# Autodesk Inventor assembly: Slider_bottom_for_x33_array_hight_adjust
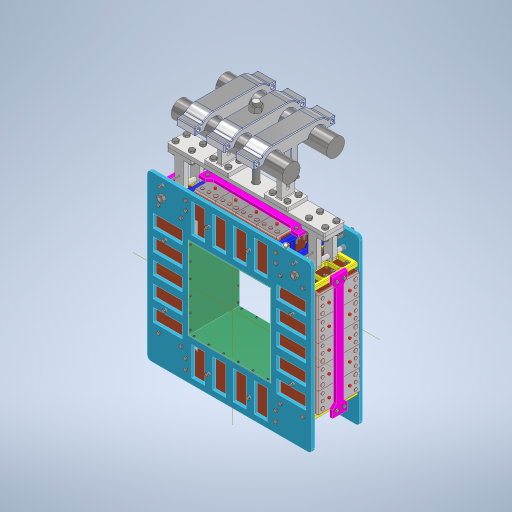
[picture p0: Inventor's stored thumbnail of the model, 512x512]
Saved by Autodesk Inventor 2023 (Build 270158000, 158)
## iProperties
Created: 2022-09
Part Number: Slider_bottom_for_x33_array_hight_adjust
Material: Aluminum 6061
Document SubType Name: Modeling
Designer: tornqvih
Mass: 680.873 g
Surface Area: 393.631 cm^2
Volume: 252.175 cm^3
Density: 2.7 g/cm^3
Appearance: Default
Sending System: Autodesk Inventor 2021
Preprocessor: ST-DEVELOPER v18.1
Title: C:\Users\Oleksii\Documents\Inventor\Scintillators_for_ISS\Part\ISSKUL9_v2.stp
Author: Oleksii
Part Number: Slider_bottom_for_x33_array
Mass: 854.06 g
Surface Area: 503.636 cm^2
Volume: 316.319 cm^3
Title: C:\Users\Oleksii\Documents\Inventor\Scintillators_for_ISS\Part\ISSKUL8_v2.stp
Created: 2023-10
Part Number: CeBr3Holder4x5
Document SubType Name: Assembly
Mass: 47327.2 g
Surface Area: 29304.1 cm^2
Volume: 17682.9 cm^3
Density: 2.67644 g/cm^3
Author: tornqvih
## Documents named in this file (37)
- \\Mac\Home\Documents\chalmers\Inventor2023\CeBr3Holder4x5\CeBr3Holder4x5.iam
- \\Mac\Home\Documents\chalmers\Inventor2023\CeBr3Holder4x5\FrontPlate.ipt
- \\Mac\Home\Documents\chalmers\Inventor2023\CeBr3Holder4x5\ShieldTop.ipt
- \\Mac\Home\Documents\chalmers\Inventor2023\CeBr3Holder4x5\ShieldLeft.ipt
- \\Mac\Home\Documents\chalmers\Inventor2023\CeBr3Holder4x5\SupportHorizontal.ipt
- \\Mac\Home\Documents\chalmers\Inventor2023\CeBr3Holder4x5\SupportVertical.ipt
- \\Mac\Home\Documents\chalmers\Inventor2023\CeBr3Holder4x5\BarHorizontal.ipt
- \\Mac\Home\Documents\chalmers\Inventor2023\CeBr3Holder4x5\BarVertical.ipt
- \\Mac\Home\Documents\chalmers\Inventor2023\CeBr3Holder4x5\CeBr3.ipt
- \\Mac\Home\Documents\Inventor\Content Center Files\R2023\en-US\AS 1110\AS 1110 - M5 x 25.ipt
- \\Mac\Home\Documents\Inventor\Content Center Files\R2023\en-US\AS 1112 (2)\AS 1112 - M5  Type 5.ipt
- \\Mac\Home\Documents\Inventor\Content Center Files\R2023\en-US\AS 1427(05)\AS 1427 - M2.5 x 8(5) II.ipt
- \\Mac\Home\Documents\Inventor\Content Center Files\R2023\en-US\AS 1110\AS 1110 - M5 x 35.ipt
- \\Mac\Home\Documents\Inventor\Content Center Files\R2023\en-US\AS 1110\AS 1110 - M5 x 40.ipt
- \\Mac\Home\Documents\Inventor\Content Center Files\R2023\en-US\ANSI B18.2.4.2M\ANSI B18.2.4.2M - M5x0.8 - 8.ipt
- \\Mac\Home\Documents\chalmers\Inventor2023\CeBr3Holder4x5\PressTopBottom.ipt
- \\Mac\Home\Documents\chalmers\Inventor2023\CeBr3Holder4x5\PressRightLeft.ipt
- \\Mac\Home\Documents\chalmers\Inventor2023\CeBr3Holder4x5\PressSide.ipt
- \\Mac\Home\Documents\Inventor\Content Center Files\R2023\en-US\AS 1474(1)\AS 1474 - M5(1).ipt
- \\Mac\Home\Documents\Inventor\Content Center Files\R2023\en-US\AS 1110\AS 1110 - M5 x 20.ipt
- **\\Mac\Home\Documents\chalmers\Inventor2023\CeBr3Holder4x5\CeBr3Holder4x5.iam*LocalDocs*xAaaaqoaaAaaaaaaaAaaaqnqtPb*ISSKUL8_v2.ipt
- **\\Mac\Home\Documents\chalmers\Inventor2023\CeBr3Holder4x5\CeBr3Holder4x5.iam*LocalDocs*xAaaaarbaAaaaaaaaAaaaqtyoWc*ISSKUL9_v2.ipt
- \\Mac\Home\Documents\chalmers\Inventor2023\CeBr3Holder4x5\HangerSlide.ipt
- \\Mac\Home\Documents\chalmers\Inventor2023\CeBr3Holder4x5\ThreadedRod.ipt
- \\Mac\Home\Documents\Inventor\Content Center Files\R2023\en-US\AS 1112 (2)\AS 1112 - M10  Type 5.ipt
- \\Mac\Home\Documents\chalmers\Inventor2023\CeBr3Holder4x5\HangerSlideHorizontal.ipt
- \\Mac\Home\Documents\chalmers\Inventor2023\CeBr3Holder4x5\HangerHorizontal.ipt
- \\Mac\Home\Documents\chalmers\Inventor2023\CeBr3Holder4x5\Roller.ipt
- \\Mac\Home\Documents\Inventor\Content Center Files\R2023\en-US\AS 1110\AS 1110 - M6 x 60.ipt
- \\Mac\Home\Documents\Inventor\Content Center Files\R2023\en-US\AS 1112 (2)\AS 1112 - M6  Type 5.ipt
- \\Mac\Home\Documents\Inventor\Content Center Files\R2023\en-US\AS 1110\AS 1110 - M8 x 30.ipt
- \\Mac\Home\Documents\Inventor\Content Center Files\R2023\en-US\AS 1112 (2)\AS 1112 - M8  Type 5.ipt
- \\Mac\Home\Documents\Inventor\Content Center Files\R2023\en-US\AS 1110\AS 1110 - M5 x 50.ipt
- \\Mac\Home\Documents\chalmers\Inventor2023\CeBr3Holder4x5\ThreadedHeight.ipt
- \\Mac\Home\Documents\Inventor\Content Center Files\R2023\en-US\AS 1112 (2)\AS 1112 - M16  Type 5.ipt
- \\Mac\Home\Documents\chalmers\Inventor2023\ISSKUL_v2\ISSKUL8_v2.stp
- \\Mac\Home\Documents\chalmers\Inventor2023\ISSKUL_v2\ISSKUL9_v2.stp
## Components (301 placed, 54 different names)
1. FrontPlate
2. BackPlate
3. ShieldTop
4. ShieldBottom
5. ShieldLeft
6. ShieldRight
7. SupportHorizontalTR
8. SupportHorizontalTL
9. SupportHorizontalBL
10. SupportHorizontalBR
11. SupportVerticalTR
12. SupportVerticalTL
13. SupportVerticalBL
14. SupportVerticalBR
15. BarHorizontalTop — Mate:351, Mate:372
16. BarHorizontalBottom — Mate:350
17. BarVerticalRight — Mate:356
18. BarVerticalLeft — Mate:359
19. CeBr3:1 — Mate:138, Mate:139, Mate:140, Mate:143, Mate:151, Mate:351
20. CeBr3:2 — Mate:141, Mate:142, Mate:143, Mate:146, Mate:154
21. CeBr3:3 — Mate:144, Mate:145, Mate:146, Mate:149, Mate:157
22. CeBr3:4 — Mate:147, Mate:148, Mate:149, Mate:160, Mate:269
23. CeBr3:5 — Mate:150, Mate:151, Mate:152, Mate:155, Mate:257, Mate:277
24. CeBr3:6 — Mate:153, Mate:154, Mate:155, Mate:158
25. CeBr3:7 — Mate:156, Mate:157, Mate:158, Mate:161
26. CeBr3:8 — Mate:159, Mate:160, Mate:161
27. CeBr3:9 — Mate:162, Mate:163, Mate:164, Mate:167, Mate:175
28. CeBr3:10 — Mate:165, Mate:166, Mate:167, Mate:170, Mate:178
29. CeBr3:11 — Mate:168, Mate:169, Mate:170, Mate:173, Mate:181
30. CeBr3:12 — Mate:171, Mate:172, Mate:173, Mate:184, Mate:272
31. CeBr3:13 — Mate:174, Mate:175, Mate:176, Mate:179, Mate:260
32. CeBr3:14 — Mate:177, Mate:178, Mate:179, Mate:182
33. CeBr3:15 — Mate:180, Mate:181, Mate:182, Mate:185
34. CeBr3:16 — Mate:183, Mate:184, Mate:185, Mate:350
35. CeBr3:17 — Mate:186, Mate:187, Mate:188, Mate:191, Mate:202, Mate:359
36. CeBr3:18 — Mate:189, Mate:190, Mate:191, Mate:194, Mate:205
37. CeBr3:19 — Mate:192, Mate:193, Mate:194, Mate:197, Mate:208
38. CeBr3:20 — Mate:195, Mate:196, Mate:197, Mate:200, Mate:211
39. CeBr3:21 — Mate:198, Mate:199, Mate:200, Mate:214, Mate:278
40. CeBr3:22 — Mate:201, Mate:202, Mate:203, Mate:206, Mate:266
41. CeBr3:23 — Mate:204, Mate:205, Mate:206, Mate:209
42. CeBr3:24 — Mate:207, Mate:208, Mate:209, Mate:212
43. CeBr3:25 — Mate:210, Mate:211, Mate:212, Mate:215
44. CeBr3:26 — Mate:213, Mate:214, Mate:215
45. CeBr3:27 — Mate:216, Mate:217, Mate:218, Mate:221, Mate:232, Mate:356
46. CeBr3:28 — Mate:219, Mate:220, Mate:221, Mate:224, Mate:235
47. CeBr3:29 — Mate:222, Mate:223, Mate:224, Mate:227, Mate:238
48. CeBr3:30 — Mate:225, Mate:226, Mate:227, Mate:230, Mate:241
49. CeBr3:31 — Mate:228, Mate:229, Mate:230, Mate:244, Mate:275
50. CeBr3:32 — Mate:231, Mate:232, Mate:233, Mate:236, Mate:263
51. CeBr3:33 — Mate:234, Mate:235, Mate:236, Mate:239
52. CeBr3:34 — Mate:237, Mate:238, Mate:239, Mate:242
53. CeBr3:35 — Mate:240, Mate:241, Mate:242, Mate:245
54. CeBr3:36 — Mate:243, Mate:244, Mate:245
55. AS 1110 - Metric M5 x 25:1
56. AS 1110 - Metric M5 x 25:2
57. AS 1110 - Metric M5 x 25:3
58. AS 1110 - Metric M5 x 25:4
59. AS 1110 - Metric M5 x 25:5
60. AS 1110 - Metric M5 x 25:6
61. AS 1110 - Metric M5 x 25:7
62. AS 1110 - Metric M5 x 25:8
63. AS 1110 - Metric M5 x 25:9
64. AS 1110 - Metric M5 x 25:10
65. AS 1110 - Metric M5 x 25:11
66. AS 1110 - Metric M5 x 25:12
67. AS 1110 - Metric M5 x 25:13
68. AS 1110 - Metric M5 x 25:14
69. AS 1110 - Metric M5 x 25:15
70. AS 1110 - Metric M5 x 25:16
71. AS 1110 - Metric M5 x 25:17
72. AS 1110 - Metric M5 x 25:18
73. AS 1110 - Metric M5 x 25:19
74. AS 1110 - Metric M5 x 25:20
75. AS 1110 - Metric M5 x 25:21
76. AS 1110 - Metric M5 x 25:22
77. AS 1110 - Metric M5 x 25:23
78. AS 1110 - Metric M5 x 25:24
79. AS 1110 - Metric M5 x 25:25
80. AS 1110 - Metric M5 x 25:26
81. AS 1110 - Metric M5 x 25:27
82. AS 1110 - Metric M5 x 25:28
83. AS 1110 - Metric M5 x 25:29
84. AS 1110 - Metric M5 x 25:30
85. AS 1110 - Metric M5 x 25:31
86. AS 1110 - Metric M5 x 25:32
87. AS 1112 (2) - Metric M5  Type 5:1
88. AS 1112 (2) - Metric M5  Type 5:2
89. AS 1112 (2) - Metric M5  Type 5:3
90. AS 1112 (2) - Metric M5  Type 5:4
91. AS 1112 (2) - Metric M5  Type 5:5
92. AS 1112 (2) - Metric M5  Type 5:6
93. AS 1112 (2) - Metric M5  Type 5:7
94. AS 1112 (2) - Metric M5  Type 5:8
95. AS 1112 (2) - Metric M5  Type 5:9
96. AS 1112 (2) - Metric M5  Type 5:10
97. AS 1112 (2) - Metric M5  Type 5:11
98. AS 1112 (2) - Metric M5  Type 5:12
99. AS 1112 (2) - Metric M5  Type 5:13
100. AS 1112 (2) - Metric M5  Type 5:14
101. AS 1112 (2) - Metric M5  Type 5:15
102. AS 1112 (2) - Metric M5  Type 5:16
103. AS 1112 (2) - Metric M5  Type 5:17
104. AS 1112 (2) - Metric M5  Type 5:18
105. AS 1112 (2) - Metric M5  Type 5:19
106. AS 1112 (2) - Metric M5  Type 5:20
107. AS 1112 (2) - Metric M5  Type 5:21
108. AS 1112 (2) - Metric M5  Type 5:22
109. AS 1112 (2) - Metric M5  Type 5:23
110. AS 1112 (2) - Metric M5  Type 5:24
111. AS 1112 (2) - Metric M5  Type 5:25
112. AS 1112 (2) - Metric M5  Type 5:26
113. AS 1112 (2) - Metric M5  Type 5:27
114. AS 1112 (2) - Metric M5  Type 5:28
115. AS 1112 (2) - Metric M5  Type 5:29
116. AS 1112 (2) - Metric M5  Type 5:30
117. AS 1112 (2) - Metric M5  Type 5:31
118. AS 1112 (2) - Metric M5  Type 5:32
119. AS 1427 H - Metric M2.5 x 8:1
120. AS 1427 H - Metric M2.5 x 8:2
121. AS 1427 H - Metric M2.5 x 8:3
122. AS 1427 H - Metric M2.5 x 8:4
123. AS 1427 H - Metric M2.5 x 8:5
124. AS 1427 H - Metric M2.5 x 8:6
125. AS 1427 H - Metric M2.5 x 8:7
126. AS 1427 H - Metric M2.5 x 8:8
127. AS 1427 H - Metric M2.5 x 8:9
128. AS 1427 H - Metric M2.5 x 8:10
129. AS 1427 H - Metric M2.5 x 8:11
130. AS 1427 H - Metric M2.5 x 8:12
131. AS 1427 H - Metric M2.5 x 8:13
132. AS 1427 H - Metric M2.5 x 8:14
133. AS 1427 H - Metric M2.5 x 8:15
134. AS 1427 H - Metric M2.5 x 8:16
135. AS 1427 H - Metric M2.5 x 8:17
136. AS 1427 H - Metric M2.5 x 8:18
137. AS 1427 H - Metric M2.5 x 8:19
138. AS 1427 H - Metric M2.5 x 8:20
139. AS 1427 H - Metric M2.5 x 8:21
140. AS 1427 H - Metric M2.5 x 8:22
141. AS 1427 H - Metric M2.5 x 8:23
142. AS 1427 H - Metric M2.5 x 8:24
143. AS 1427 H - Metric M2.5 x 8:25
144. AS 1427 H - Metric M2.5 x 8:26
145. AS 1427 H - Metric M2.5 x 8:27
146. AS 1427 H - Metric M2.5 x 8:28
147. AS 1427 H - Metric M2.5 x 8:29
148. AS 1427 H - Metric M2.5 x 8:30
149. AS 1427 H - Metric M2.5 x 8:31
150. AS 1427 H - Metric M2.5 x 8:32
151. AS 1427 H - Metric M2.5 x 8:33
152. AS 1427 H - Metric M2.5 x 8:34
153. AS 1427 H - Metric M2.5 x 8:35
154. AS 1427 H - Metric M2.5 x 8:36
155. AS 1427 H - Metric M2.5 x 8:37
156. AS 1427 H - Metric M2.5 x 8:38
157. AS 1427 H - Metric M2.5 x 8:39
158. AS 1427 H - Metric M2.5 x 8:40
159. AS 1427 H - Metric M2.5 x 8:41
160. AS 1427 H - Metric M2.5 x 8:42
161. AS 1427 H - Metric M2.5 x 8:43
162. AS 1427 H - Metric M2.5 x 8:44
163. AS 1427 H - Metric M2.5 x 8:45
164. AS 1427 H - Metric M2.5 x 8:46
165. AS 1427 H - Metric M2.5 x 8:47
166. AS 1427 H - Metric M2.5 x 8:48
167. AS 1110 - Metric M5 x 35:25 — Mate:355
168. AS 1110 - Metric M5 x 35:3
169. AS 1110 - Metric M5 x 35:5 — Mate:352, Mate:372
170. AS 1110 - Metric M5 x 35:6
171. AS 1110 - Metric M5 x 35:7 — Mate:353
172. AS 1110 - Metric M5 x 35:9
173. AS 1110 - Metric M5 x 35:11 — Mate:354
174. AS 1110 - Metric M5 x 35:12
175. AS 1110 - Metric M5 x 35:13 — Mate:358
176. AS 1110 - Metric M5 x 35:15
177. AS 1110 - Metric M5 x 35:16 — Mate:357
178. AS 1110 - Metric M5 x 35:18
179. AS 1110 - Metric M5 x 40:1 — Mate:361
180. AS 1110 - Metric M5 x 40:3
181. AS 1110 - Metric M5 x 40:4 — Mate:360
182. AS 1110 - Metric M5 x 40:6
183. ANSI B18.2.4.2M M5x0.8:1
184. ANSI B18.2.4.2M M5x0.8:3
185. ANSI B18.2.4.2M M5x0.8:4
186. ANSI B18.2.4.2M M5x0.8:6
187. ANSI B18.2.4.2M M5x0.8:7
188. ANSI B18.2.4.2M M5x0.8:9
189. ANSI B18.2.4.2M M5x0.8:10
190. ANSI B18.2.4.2M M5x0.8:12
191. ANSI B18.2.4.2M M5x0.8:13
192. ANSI B18.2.4.2M M5x0.8:15
193. ANSI B18.2.4.2M M5x0.8:16
194. ANSI B18.2.4.2M M5x0.8:18
195. ANSI B18.2.4.2M M5x0.8:19
196. ANSI B18.2.4.2M M5x0.8:21
197. ANSI B18.2.4.2M M5x0.8:22
198. ANSI B18.2.4.2M M5x0.8:24
199. PressTop — Mate:256, Mate:257, Mate:258, Mate:280, Mate:282
200. PressBottom — Mate:259, Mate:260, Mate:261, Mate:288, Mate:290
201. PressRight — Mate:262, Mate:263, Mate:264, Mate:284, Mate:286
202. PressLef — Mate:265, Mate:266, Mate:267, Mate:292, Mate:294
203. PressSideTop — Mate:268, Mate:269, Mate:270, Mate:274, Mate:296, Mate:298
204. PressSideBottom — Mate:271, Mate:272, Mate:273, Mate:304, Mate:306
205. PressSideRight — Mate:274, Mate:275, Mate:276, Mate:300, Mate:302
206. PressSideLeft — Mate:277, Mate:278, Mate:279, Mate:308, Mate:310
207. AS 1474 - Metric M5:1
208. AS 1474 - Metric M5:2
209. AS 1474 - Metric M5:3
210. AS 1474 - Metric M5:4
211. AS 1474 - Metric M5:5
212. AS 1474 - Metric M5:6
213. AS 1474 - Metric M5:7
214. AS 1474 - Metric M5:8
215. AS 1474 - Metric M5:9
216. AS 1474 - Metric M5:10
217. AS 1474 - Metric M5:11
218. AS 1474 - Metric M5:12
219. AS 1474 - Metric M5:13
220. AS 1474 - Metric M5:14
221. AS 1474 - Metric M5:15
222. AS 1474 - Metric M5:16
223. AS 1110 - Metric M5 x 20:33 — Mate:280, Mate:281
224. AS 1110 - Metric M5 x 20:2 — Mate:282, Mate:283
225. AS 1110 - Metric M5 x 20:3 — Mate:284, Mate:285
226. AS 1110 - Metric M5 x 20:4 — Mate:286, Mate:287
227. AS 1110 - Metric M5 x 20:5 — Mate:288, Mate:289
228. AS 1110 - Metric M5 x 20:6 — Mate:290, Mate:291
229. AS 1110 - Metric M5 x 20:7 — Mate:292, Mate:293
230. AS 1110 - Metric M5 x 20:8 — Mate:294, Mate:295
231. AS 1110 - Metric M5 x 20:9 — Mate:296, Mate:297
232. AS 1110 - Metric M5 x 20:10 — Mate:298, Mate:299
233. AS 1110 - Metric M5 x 20:11 — Mate:300, Mate:301
234. AS 1110 - Metric M5 x 20:12 — Mate:302, Mate:303
235. AS 1110 - Metric M5 x 20:13 — Mate:304, Mate:305
236. AS 1110 - Metric M5 x 20:14 — Mate:306, Mate:307
237. AS 1110 - Metric M5 x 20:15 — Mate:308, Mate:309
238. AS 1110 - Metric M5 x 20:16 — Mate:310, Mate:311
239. ISSKUL8_v2:1
240. ISSKUL8_v2:2 — Mate:314, Mate:333, Mate:336, Mate:339, Mate:343
241. ISSKUL9_v2:1 — Mate:337, Mate:340, Mate:373
242. HangerSlideRight
243. HangerSlideLeft
244. ThreadedRodRight — Mate:316, Flush:314, Mate:318
245. ThreadedRodLeft — Mate:317, Flush:315, Mate:319
246. AS 1112 (2) - Metric M10  Type 5:1
247. AS 1112 (2) - Metric M10  Type 5:2
248. AS 1112 (2) - Metric M10  Type 5:3
249. AS 1112 (2) - Metric M10  Type 5:4
250. HangerSlideHorizontalRight
251. HangerSlideHorizontalLeft
252. HangerHorizontal
253. RollerFront
254. RollerBack — Mate:339, Mate:340, Mate:341, Flush:317, Angle:1, Mate:362
255. AS 1110 - Metric M6 x 60:1
256. AS 1110 - Metric M6 x 60:2
257. AS 1112 (2) - Metric M6  Type 5:1 — Mate:343
258. AS 1112 (2) - Metric M6  Type 5:2 — Mate:345
259. AS 1110 - Metric M8 x 30:9
260. AS 1110 - Metric M8 x 30:10
261. AS 1110 - Metric M8 x 30:11
262. AS 1110 - Metric M8 x 30:12
263. AS 1110 - Metric M8 x 30:13
264. AS 1110 - Metric M8 x 30:14
265. AS 1110 - Metric M8 x 30:15
266. AS 1110 - Metric M8 x 30:16
267. AS 1110 - Metric M8 x 30:1
268. AS 1110 - Metric M8 x 30:2
269. AS 1110 - Metric M8 x 30:3
270. AS 1110 - Metric M8 x 30:4
271. AS 1110 - Metric M8 x 30:5
272. AS 1110 - Metric M8 x 30:6
273. AS 1110 - Metric M8 x 30:7
274. AS 1110 - Metric M8 x 30:8
275. AS 1112 (2) - Metric M8  Type 5:1
276. AS 1112 (2) - Metric M8  Type 5:2
277. AS 1112 (2) - Metric M8  Type 5:3
278. AS 1112 (2) - Metric M8  Type 5:4
279. AS 1112 (2) - Metric M8  Type 5:5
280. AS 1112 (2) - Metric M8  Type 5:6
281. AS 1112 (2) - Metric M8  Type 5:7
282. AS 1112 (2) - Metric M8  Type 5:8
283. AS 1112 (2) - Metric M8  Type 5:9
284. AS 1112 (2) - Metric M8  Type 5:10
285. AS 1112 (2) - Metric M8  Type 5:11
286. AS 1112 (2) - Metric M8  Type 5:12
287. AS 1112 (2) - Metric M8  Type 5:13
288. AS 1112 (2) - Metric M8  Type 5:14
289. AS 1112 (2) - Metric M8  Type 5:15
290. AS 1112 (2) - Metric M8  Type 5:16
291. AS 1110 - Metric M5 x 50:1 — Mate:364
292. AS 1110 - Metric M5 x 50:2 — Mate:366
293. AS 1110 - Metric M5 x 50:3 — Mate:370
294. AS 1110 - Metric M5 x 50:4 — Mate:371
295. AS 1474 - Metric M5:17
296. AS 1474 - Metric M5:18
297. AS 1474 - Metric M5:19
298. AS 1474 - Metric M5:20
299. ThreadedHeight:1 — Mate:373, Mate:374, Flush:318
300. AS 1112 (2) - Metric M16  Type 5:1
301. AS 1112 (2) - Metric M16  Type 5:2
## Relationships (202: Mate 197, Flush 4, Angle 1)
- Mate:138: CeBr3:1
- Mate:139: CeBr3:1
- Mate:140: CeBr3:1
- Mate:141: CeBr3:2
- Mate:142: CeBr3:2
- Mate:143: CeBr3:1 ↔ CeBr3:2
- Mate:144: CeBr3:3
- Mate:145: CeBr3:3
- Mate:146: CeBr3:2 ↔ CeBr3:3
- Mate:147: CeBr3:4
- Mate:148: CeBr3:4
- Mate:149: CeBr3:3 ↔ CeBr3:4
- Mate:150: CeBr3:5
- Mate:151: CeBr3:1 ↔ CeBr3:5
- Mate:152: CeBr3:5
- Mate:153: CeBr3:6
- Mate:154: CeBr3:2 ↔ CeBr3:6
- Mate:155: CeBr3:5 ↔ CeBr3:6
- Mate:156: CeBr3:7
- Mate:157: CeBr3:3 ↔ CeBr3:7
- Mate:158: CeBr3:6 ↔ CeBr3:7
- Mate:159: CeBr3:8
- Mate:160: CeBr3:4 ↔ CeBr3:8
- Mate:161: CeBr3:7 ↔ CeBr3:8
- Mate:162: CeBr3:9
- Mate:163: CeBr3:9
- Mate:164: CeBr3:9
- Mate:165: CeBr3:10
- Mate:166: CeBr3:10
- Mate:167: CeBr3:9 ↔ CeBr3:10
- Mate:168: CeBr3:11
- Mate:169: CeBr3:11
- Mate:170: CeBr3:10 ↔ CeBr3:11
- Mate:171: CeBr3:12
- Mate:172: CeBr3:12
- Mate:173: CeBr3:11 ↔ CeBr3:12
- Mate:174: CeBr3:13
- Mate:175: CeBr3:9 ↔ CeBr3:13
- Mate:176: CeBr3:13
- Mate:177: CeBr3:14
- Mate:178: CeBr3:10 ↔ CeBr3:14
- Mate:179: CeBr3:13 ↔ CeBr3:14
- Mate:180: CeBr3:15
- Mate:181: CeBr3:11 ↔ CeBr3:15
- Mate:182: CeBr3:14 ↔ CeBr3:15
- Mate:183: CeBr3:16
- Mate:184: CeBr3:12 ↔ CeBr3:16
- Mate:185: CeBr3:15 ↔ CeBr3:16
- Mate:186: CeBr3:17
- Mate:187: CeBr3:17
- Mate:188: CeBr3:17
- Mate:189: CeBr3:18
- Mate:190: CeBr3:18
- Mate:191: CeBr3:17 ↔ CeBr3:18
- Mate:192: CeBr3:19
- Mate:193: CeBr3:19
- Mate:194: CeBr3:18 ↔ CeBr3:19
- Mate:195: CeBr3:20
- Mate:196: CeBr3:20
- Mate:197: CeBr3:19 ↔ CeBr3:20
- Mate:198: CeBr3:21
- Mate:199: CeBr3:21
- Mate:200: CeBr3:20 ↔ CeBr3:21
- Mate:201: CeBr3:22
- Mate:202: CeBr3:17 ↔ CeBr3:22
- Mate:203: CeBr3:22
- Mate:204: CeBr3:23
- Mate:205: CeBr3:18 ↔ CeBr3:23
- Mate:206: CeBr3:22 ↔ CeBr3:23
- Mate:207: CeBr3:24
- Mate:208: CeBr3:19 ↔ CeBr3:24
- Mate:209: CeBr3:23 ↔ CeBr3:24
- Mate:210: CeBr3:25
- Mate:211: CeBr3:20 ↔ CeBr3:25
- Mate:212: CeBr3:24 ↔ CeBr3:25
- Mate:213: CeBr3:26
- Mate:214: CeBr3:21 ↔ CeBr3:26
- Mate:215: CeBr3:25 ↔ CeBr3:26
- Mate:216: CeBr3:27
- Mate:217: CeBr3:27
- Mate:218: CeBr3:27
- Mate:219: CeBr3:28
- Mate:220: CeBr3:28
- Mate:221: CeBr3:27 ↔ CeBr3:28
- Mate:222: CeBr3:29
- Mate:223: CeBr3:29
- Mate:224: CeBr3:28 ↔ CeBr3:29
- Mate:225: CeBr3:30
- Mate:226: CeBr3:30
- Mate:227: CeBr3:29 ↔ CeBr3:30
- Mate:228: CeBr3:31
- Mate:229: CeBr3:31
- Mate:230: CeBr3:30 ↔ CeBr3:31
- Mate:231: CeBr3:32
- Mate:232: CeBr3:27 ↔ CeBr3:32
- Mate:233: CeBr3:32
- Mate:234: CeBr3:33
- Mate:235: CeBr3:28 ↔ CeBr3:33
- Mate:236: CeBr3:32 ↔ CeBr3:33
- Mate:237: CeBr3:34
- Mate:238: CeBr3:29 ↔ CeBr3:34
- Mate:239: CeBr3:33 ↔ CeBr3:34
- Mate:240: CeBr3:35
- Mate:241: CeBr3:30 ↔ CeBr3:35
- Mate:242: CeBr3:34 ↔ CeBr3:35
- Mate:243: CeBr3:36
- Mate:244: CeBr3:31 ↔ CeBr3:36
- Mate:245: CeBr3:35 ↔ CeBr3:36
- Mate:256: PressTop
- Mate:257: CeBr3:5 ↔ PressTop
- Mate:258: PressTop
- Mate:259: PressBottom
- Mate:260: CeBr3:13 ↔ PressBottom
- Mate:261: PressBottom
- Mate:262: PressRight
- Mate:263: CeBr3:32 ↔ PressRight
- Mate:264: PressRight
- Mate:265: PressLef
- Mate:266: CeBr3:22 ↔ PressLef
- Mate:267: PressLef
- Mate:268: PressSideTop
- Mate:269: CeBr3:4 ↔ PressSideTop
- Mate:270: PressSideTop
- Mate:271: PressSideBottom
- Mate:272: CeBr3:12 ↔ PressSideBottom
- Mate:273: PressSideBottom
- Mate:274: PressSideTop ↔ PressSideRight
- Mate:275: CeBr3:31 ↔ PressSideRight
- Mate:276: PressSideRight
- Mate:277: CeBr3:5 ↔ PressSideLeft
- Mate:278: CeBr3:21 ↔ PressSideLeft
- Mate:279: PressSideLeft
- Mate:280: PressTop ↔ AS 1110 - Metric M5 x 20:33
- Mate:281: AS 1110 - Metric M5 x 20:33
- Mate:282: PressTop ↔ AS 1110 - Metric M5 x 20:2
- Mate:283: AS 1110 - Metric M5 x 20:2
- Mate:284: PressRight ↔ AS 1110 - Metric M5 x 20:3
- Mate:285: AS 1110 - Metric M5 x 20:3
- Mate:286: PressRight ↔ AS 1110 - Metric M5 x 20:4
- Mate:287: AS 1110 - Metric M5 x 20:4
- Mate:288: PressBottom ↔ AS 1110 - Metric M5 x 20:5
- Mate:289: AS 1110 - Metric M5 x 20:5
- Mate:290: PressBottom ↔ AS 1110 - Metric M5 x 20:6
- Mate:291: AS 1110 - Metric M5 x 20:6
- Mate:292: PressLef ↔ AS 1110 - Metric M5 x 20:7
- Mate:293: AS 1110 - Metric M5 x 20:7
- Mate:294: PressLef ↔ AS 1110 - Metric M5 x 20:8
- Mate:295: AS 1110 - Metric M5 x 20:8
- Mate:296: PressSideTop ↔ AS 1110 - Metric M5 x 20:9
- Mate:297: AS 1110 - Metric M5 x 20:9
- Mate:298: PressSideTop ↔ AS 1110 - Metric M5 x 20:10
- Mate:299: AS 1110 - Metric M5 x 20:10
- Mate:300: PressSideRight ↔ AS 1110 - Metric M5 x 20:11
- Mate:301: AS 1110 - Metric M5 x 20:11
- Mate:302: PressSideRight ↔ AS 1110 - Metric M5 x 20:12
- Mate:303: AS 1110 - Metric M5 x 20:12
- Mate:304: PressSideBottom ↔ AS 1110 - Metric M5 x 20:13
- Mate:305: AS 1110 - Metric M5 x 20:13
- Mate:306: PressSideBottom ↔ AS 1110 - Metric M5 x 20:14
- Mate:307: AS 1110 - Metric M5 x 20:14
- Mate:308: PressSideLeft ↔ AS 1110 - Metric M5 x 20:15
- Mate:309: AS 1110 - Metric M5 x 20:15
- Mate:310: PressSideLeft ↔ AS 1110 - Metric M5 x 20:16
- Mate:311: AS 1110 - Metric M5 x 20:16
- Mate:314: ISSKUL8_v2:2
- Mate:316: ThreadedRodRight
- Flush:314: ThreadedRodRight
- Mate:317: ThreadedRodLeft
- Flush:315: ThreadedRodLeft
- Mate:318: ThreadedRodRight
- Mate:319: ThreadedRodLeft
- Mate:333: ISSKUL8_v2:2
- Mate:336: ISSKUL8_v2:2
- Mate:337: ISSKUL9_v2:1
- Mate:339: ISSKUL8_v2:2 ↔ RollerBack
- Mate:340: ISSKUL9_v2:1 ↔ RollerBack
- Mate:341: RollerBack
- Flush:317: RollerBack
- Mate:343: ISSKUL8_v2:2 ↔ AS 1112 (2) - Metric M6  Type 5:1
- Mate:345: AS 1112 (2) - Metric M6  Type 5:2
- Mate:350: BarHorizontalBottom ↔ CeBr3:16
- Mate:351: BarHorizontalTop ↔ CeBr3:1
- Mate:352: AS 1110 - Metric M5 x 35:5
- Mate:353: AS 1110 - Metric M5 x 35:7
- Mate:354: AS 1110 - Metric M5 x 35:11
- Mate:355: AS 1110 - Metric M5 x 35:25
- Mate:356: BarVerticalRight ↔ CeBr3:27
- Mate:357: AS 1110 - Metric M5 x 35:16
- Mate:358: AS 1110 - Metric M5 x 35:13
- Mate:359: BarVerticalLeft ↔ CeBr3:17
- Mate:360: AS 1110 - Metric M5 x 40:4
- Mate:361: AS 1110 - Metric M5 x 40:1
- Angle:1: RollerBack
- Mate:362: RollerBack
- Mate:364: AS 1110 - Metric M5 x 50:1
- Mate:366: AS 1110 - Metric M5 x 50:2
- Mate:370: AS 1110 - Metric M5 x 50:3
- Mate:371: AS 1110 - Metric M5 x 50:4
- Mate:372: BarHorizontalTop ↔ AS 1110 - Metric M5 x 35:5
- Mate:373: ISSKUL9_v2:1 ↔ ThreadedHeight:1
- Mate:374: ThreadedHeight:1
- Flush:318: ThreadedHeight:1
## Named parameters: sa_0 = 0 mm, sa_2 = 0
